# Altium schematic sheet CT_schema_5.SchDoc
size 299 x 271 mm
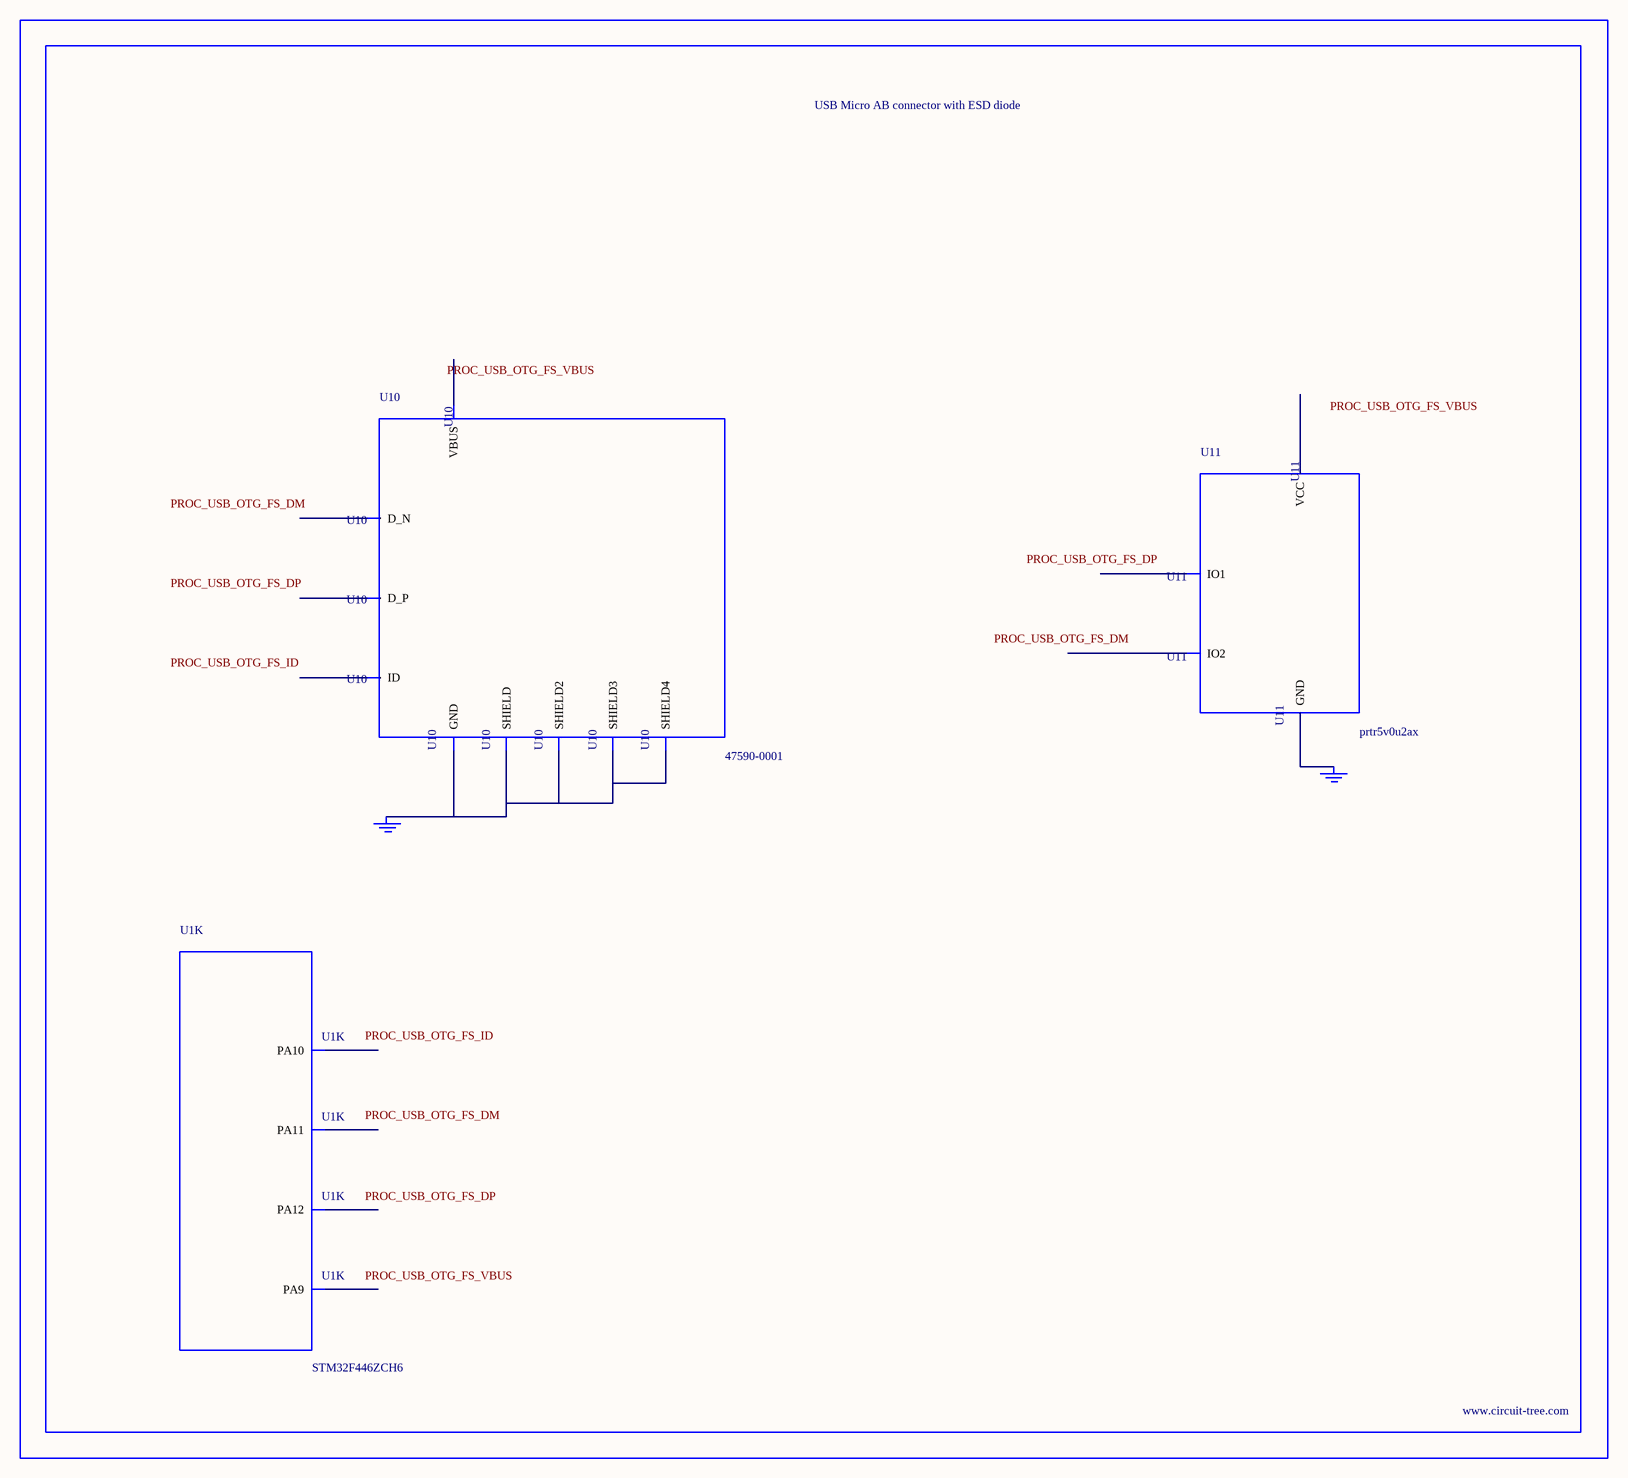
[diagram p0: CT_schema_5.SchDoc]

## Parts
BORDER4  (no value)
GND_INSTANCE_4_0  (no value)
GND_INSTANCE_4_1  (no value)
U1  STM32F446ZCH6  [UFBGA144]  (part K of 11)
U10  47590-0001  [MICRO_USB_AB]
U11  prtr5v0u2ax  [SOT143B]

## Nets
NetGND_INSTANCE_4_0_0: GND_INSTANCE_4_0.0(GND) U10.5(GND) U10.6(SHIELD) U10.7(SHIELD2) U10.8(SHIELD3) U10.9(SHIELD4)
NetGND_INSTANCE_4_1_0: GND_INSTANCE_4_1.0(GND) U11.1(GND)

Not connected (* = marked no-connect by the designer): U1 B12(PA12) C12(PA11) D11(PA10) D12(PA9); U10 1(VBUS) 2(D_N) 3(D_P) 4(ID); U11 2(IO1) 3(IO2) 4(VCC)

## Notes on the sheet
- Labels drawn without touching a wire or pin: PROC_USB_OTG_FS_DM, PROC_USB_OTG_FS_DP, PROC_USB_OTG_FS_ID, PROC_USB_OTG_FS_VBUS

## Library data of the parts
BORDER4 = BORDER_PAGE4
GND_INSTANCE_4_0 GND_INSTANCE_4_1 = GND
